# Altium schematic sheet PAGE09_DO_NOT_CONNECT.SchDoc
size 381 x 304 mm; SheetNumber: 10; SheetTotal: 28
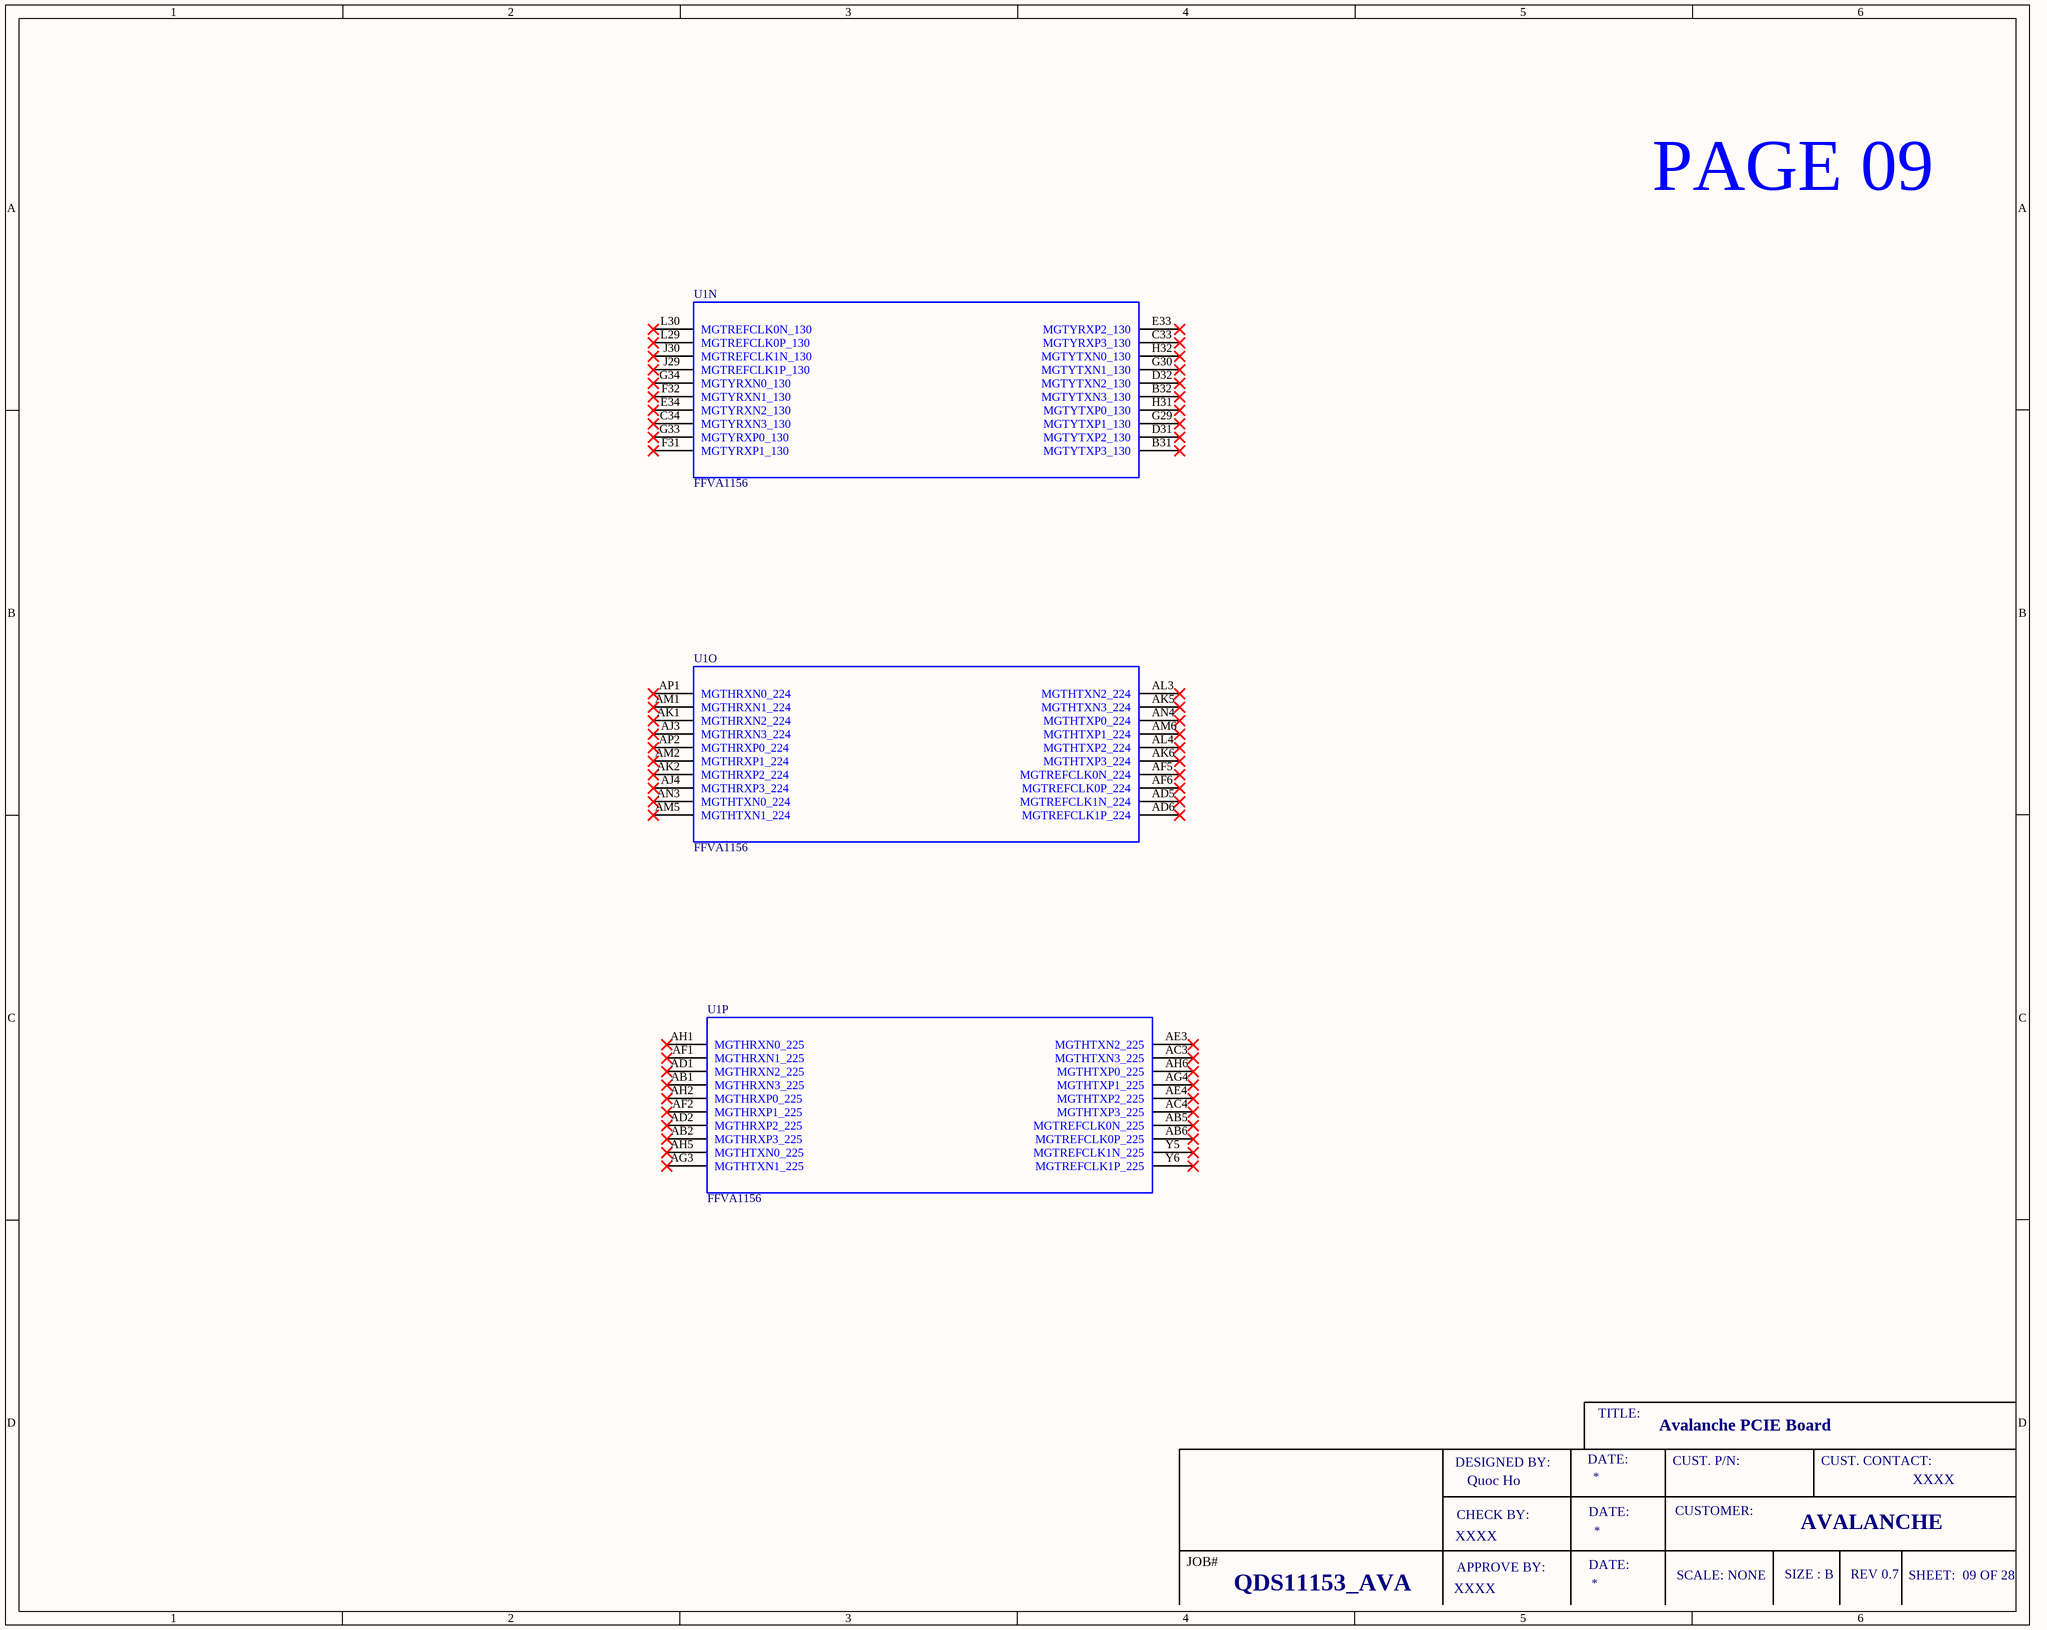
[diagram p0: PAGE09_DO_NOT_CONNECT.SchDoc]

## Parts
U1  FFVA1156  [FFVA1156]  (parts N,O,P of 25)

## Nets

Not connected (* = marked no-connect by the designer): U1 AB1(MGTHRXN3_225)* AB2(MGTHRXP3_225)* AB5(MGTREFCLK0N_225)* AB6(MGTREFCLK0P_225)* AC3(MGTHTXN3_225)* AC4(MGTHTXP3_225)* AD1(MGTHRXN2_225)* AD2(MGTHRXP2_225)* AD5(MGTREFCLK1N_224)* AD6(MGTREFCLK1P_224)* AE3(MGTHTXN2_225)* AE4(MGTHTXP2_225)* AF1(MGTHRXN1_225)* AF2(MGTHRXP1_225)* AF5(MGTREFCLK0N_224)* AF6(MGTREFCLK0P_224)* AG3(MGTHTXN1_225)* AG4(MGTHTXP1_225)* AH1(MGTHRXN0_225)* AH2(MGTHRXP0_225)* AH5(MGTHTXN0_225)* AH6(MGTHTXP0_225)* AJ3(MGTHRXN3_224)* AJ4(MGTHRXP3_224)* AK1(MGTHRXN2_224)* AK2(MGTHRXP2_224)* AK5(MGTHTXN3_224)* AK6(MGTHTXP3_224)* AL3(MGTHTXN2_224)* AL4(MGTHTXP2_224)* AM1(MGTHRXN1_224)* AM2(MGTHRXP1_224)* AM5(MGTHTXN1_224)* AM6(MGTHTXP1_224)* AN3(MGTHTXN0_224)* AN4(MGTHTXP0_224)* AP1(MGTHRXN0_224)* AP2(MGTHRXP0_224)* B31(MGTYTXP3_130)* B32(MGTYTXN3_130)* C33(MGTYRXP3_130)* C34(MGTYRXN3_130)* D31(MGTYTXP2_130)* D32(MGTYTXN2_130)* E33(MGTYRXP2_130)* E34(MGTYRXN2_130)* F31(MGTYRXP1_130)* F32(MGTYRXN1_130)* G29(MGTYTXP1_130)* G30(MGTYTXN1_130)* G33(MGTYRXP0_130)* G34(MGTYRXN0_130)* H31(MGTYTXP0_130)* H32(MGTYTXN0_130)* J29(MGTREFCLK1P_130)* J30(MGTREFCLK1N_130)* L29(MGTREFCLK0P_130)* L30(MGTREFCLK0N_130)* Y5(MGTREFCLK1N_225)* Y6(MGTREFCLK1P_225)*

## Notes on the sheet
- PAGE 09
- TITLE:
- Avalanche PCIE Board
- DESIGNED BY:
- CHECK BY:
- Quoc Ho
- DATE:
- CUST. P/N:
- CUSTOMER:
- CUST. CONTACT:
- XXXX
- JOB#
- APPROVE BY:
- SCALE: NONE
- SIZE : B
- AVALANCHE
- REV 0.7
- SHEET:  09 OF 28
- QDS11153_AVA

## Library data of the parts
U1 = FFVA1156: IC FPGA 516 I/O 1156FCBGA; Manufacturer: AMD; Manufacturer Part Number: XCKU15P-1FFVA1156E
